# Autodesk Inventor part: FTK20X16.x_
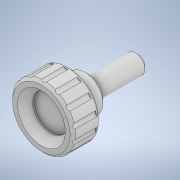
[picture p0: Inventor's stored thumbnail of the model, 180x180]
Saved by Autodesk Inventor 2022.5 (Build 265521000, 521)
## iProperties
Created: 2023-10
Part Number: FTK20X16.x_
Material: 一般
Document SubType Name: Modeling
Designer: ImaoCorp
Density: 1 g/cm^3
Appearance: 既定
Sending System: SOLIDWORKS 2021-2021301
MC: AMD64
MC_MODEL: Intel64 Family 6 Model 60 Stepping 3, GenuineIntel
OS: Windows_NT
FRU: Parasolid Version 32.1, build 255,  1- 1-2021
FORMAT: text
GUISE: transmit
KEY: FTK20X16
FILE: FTK20X16.x_t
DATE: Tue Oct 17 11:07:33 2023
Author: ImaoCorp
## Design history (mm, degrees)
feature "Base1"
node "ソリッド1"
